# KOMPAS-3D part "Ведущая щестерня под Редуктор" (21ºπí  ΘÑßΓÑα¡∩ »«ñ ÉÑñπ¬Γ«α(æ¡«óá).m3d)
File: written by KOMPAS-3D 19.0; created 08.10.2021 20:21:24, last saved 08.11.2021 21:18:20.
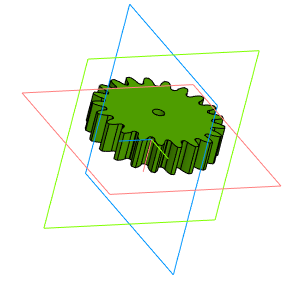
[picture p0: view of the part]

Document properties: Автор: Дымок(R); Организация: PDA-NN.3dn.ru; Полное имя файла: D:\3D_print\3D проекты Компас 3D\Редуктор (Снова)\21зуб  щестерня под Редуктор(Снова).m3d

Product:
- Part/product: Ведущая щестерня под Редуктор
    Материал: АБС 0603Т ТУ 2214-019-002 03521-96 (density 0 kg/m3)

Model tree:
1. ЛСК (Шестерня цилиндрическая с внешними зубьями):1  (with: Шестерня цилиндрическая с внешними зубьями:1, Плоскость XY, Плоскость ZX, Плоскость ZY, Ось X, Ось Y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)  (labels: &Фаска (Шестерня цилиндрическая с внешними зубьями):1)
     Ось X. X = 1; Ось Y. Y = 1; Ось Z. Z = 1; Угол 1 = 360
2. Эскиз для винтовой линии (Шестерня цилиндрическая с внешними зубьями):1  (with: Винтовая линия (Шестерня цилиндрическая с внешними зубьями):1, Шестерня цилиндрическая с внешними зубьями:1, Впадина (Шестерня цилиндрическая с внешними зубьями):1, Впадина прямая (Шестерня цилиндрическая с внешними зубьями):1, Массив косых впадин (Шестерня цилиндрическая с внешними зубьями):1)  (2 pattern instances)
     Число витков = 0.00704572; Смещение 2 = 8
3. Впадина прямая (Шестерня цилиндрическая с внешними зубьями):1  (19 pattern instances)
4. Впадина (Шестерня цилиндрическая с внешними зубьями):1  (with: Массив прямых впадин (Шестерня цилиндрическая с внешними зубьями):1, Шестерня цилиндрическая с внешними зубьями:1)  (2 pattern instances)
     N 1 = 1; Шаг 1 = 1; Номер 1 = 1
5. Впадина косая (Шестерня цилиндрическая с внешними зубьями):1  (with: Винтовая линия (Шестерня цилиндрическая с внешними зубьями):1, Впадина прямая (Шестерня цилиндрическая с внешними зубьями):1)  (19 pattern instances)
     N 1 = 1; Шаг 1 = 1; Номер 1 = 1
6. Шестерня цилиндрическая с внешними зубьями:1
7. Эскиз:5  (with: Цилиндр (Шестерня цилиндрическая с внешними зубьями):1)
8. Элемент выдавливания:3  (labels: АБС 0603Т ТУ 2214-019-002 03521-96)

Expressions: (VGExtS_1_z*VGExtS_1_M)/COSD(VGExtS_1_Beta); 360/VGExtS_1_z
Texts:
  SHAFT3D
  Количество отображаемых зубьев
  Угол наклона линии зубьев
  Шаг по кольцевому направлению
  (VGExtS_1_Beta>0)?(M_PI*VGExtS_1_z*VGExtS_1_M/SIND(VGExtS_1_Beta)):1000
  (VGExtS_1_Da<=0||VGExtS_1_Da>5e+7)?25:VGExtS_1_Da
  (VGExtS_1_H<=0||VGExtS_1_H>5e+7)?25:VGExtS_1_H
  VGExtS_1_zz<VGExtS_1_z?(VGExtS_1_zz+1):VGExtS_1_z
  (VGExtS_1_zz<=0||VGExtS_1==1)||(VGExtS_1_Beta>0)?1:0
  (VGExtS_1_zz<=0||VGExtS_1==1)||(VGExtS_1_Beta<=0)?1:0
  (VGExtS_1==1)||(VGExtS_1_Beta<=0)?1:0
